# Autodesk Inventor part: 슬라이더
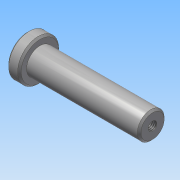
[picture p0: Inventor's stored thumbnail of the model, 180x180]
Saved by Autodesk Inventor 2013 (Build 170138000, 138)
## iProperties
Company: 한국ATC센터
Created: 2014-08
Part Number: 슬라이더
Document SubType Name: Modeling
Designer: KYOUNG IL JANG
Density: 7.86 g/cm^3
Material: 강철, 연강
Mass: 107.623 g
Surface Area: 43.9337 cm^2
Volume: 13.6925 cm^3
Author: KYOUNG IL JANG
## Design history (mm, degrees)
sketch "스케치1"
  geometry: L1 (-7, 0)-(63, 0); L2 (63, 0)-(63, 7.5); L3 (63, 7.5)-(0, 7.5); L4 (-7, 0)-(-7, 11.5); L5 (-7, 11.5)-(0, 11.5); L6 (0, 11.5)-(0, 7.5); 1 further point
  constraints: 12 end point, 3 perpendicular, 2 horizontal, 2 point on line, 1 parallel
  dimensions: "d1" = 70 distance of L1.start L1.end; "d19" = 15 diameter of L3 L1; "d20" = 7 distance of L4.end L5.end; "d21" = 23 diameter of L5 L1
revolve "회전1" stored, may be unused: angle "d4" = 90 deg
chamfer "모따기1" distance "d16" = 1; stored, may be unused: second distance "d17" = 2, angle "d18" = 45 deg
hole "구멍2" diameter "d24" = 4.917; stored, may be unused: countersink angle "d28" = 90 deg, drill point angle "d30" = 118 deg; dims "d22" = 10, "d23" = 10, "d25" = 10, "d26" = 4, "d27" = 2, "d29" = 13
node "솔리드1"
